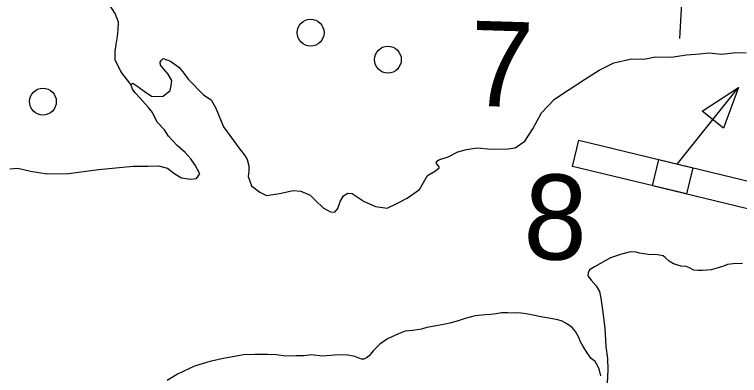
# Model space of a CAD drawing. Extents: x 653372 to 905732, y 627442 to 787275.
# Drawn here: x 702502 to 705201, y 742323 to 743667 of the extents above; entities that cross this region are included whole.
import ezdxf

# ---------------------------------------------------------------- set-up
doc = ezdxf.new("R2010")
doc.units = 0
for name, color, linetype in [('35', 7, 'Continuous'), ('5', 7, 'Continuous'), ('56', 7, 'Continuous'), ('57', 7, 'Continuous'), ('9', 7, 'Continuous')]:
    doc.layers.add(name, color=color, linetype=linetype)

msp = doc.modelspace()

# ---------------------------------------------------------------- linework, layer by layer
at = {"layer": '35'}
msp.add_lwpolyline([(702934.8, 743406.8), (702897.6, 743455.5), (702876.6, 743498.2), (702876.2, 743531.1), (702880.9, 743556), (702885.7, 743584.8), (702887.8, 743609.7), (702888.7, 743638.7), (702876.5, 743670.6), (702853.8, 743705.5), (702817.1, 743751.4), (702779.2, 743803.8), (702748.8, 743834.8)], dxfattribs=at)
at = {"layer": '5'}
msp.add_lwpolyline([(704993.4, 743866), (704977.1, 743578.3)], dxfattribs=at)
at = {"layer": '56'}
for p, q in [((705062, 743307.5), (705197.5, 743394.9)), ((705197.5, 743394.9), (705141.5, 743243.6)), ((705141.5, 743243.6), (705062, 743307.5))]:
    msp.add_line(p, q, dxfattribs=at)
msp.add_lwpolyline([(704969.1, 743110.4), (705197.5, 743394.9)], dxfattribs=at)
for points in [[(704578.7, 743101.8), (704602.2, 743199), (705027.5, 743096.3), (705004, 742999.1)], [(704876.9, 743029.8), (704900.4, 743127), (705325.7, 743024.2), (705302.2, 742927)]]:
    msp.add_lwpolyline(points, close=True, dxfattribs=at)
for centre in [(703604.2, 743599.6), (703891.9, 743499.2), (702607.6, 743343)]:
    msp.add_circle(centre, 50, dxfattribs=at)
at = {"layer": '9'}
for points in [[(703759, 743000.4), (703803.2, 742971.5), (703845.9, 742951.9), (703889, 742946.6), (703927.6, 742965.2), (703963.6, 742983.8), (704009.1, 743015.2), (704039.5, 743068.1), (704068.9, 743085.5), (704082.4, 743096.9), (704082.4, 743099.6), (704072.4, 743113), (704072.5, 743119.5), (704081.9, 743125.8), (704116.4, 743137.9), (704152.3, 743156.5), (704184.1, 743164.7), (704224.9, 743171.4), (704277.2, 743165.9), (704340.2, 743166.6), (704365.2, 743171.1), (704401.4, 743196.2), (704431.6, 743241.2), (704463.5, 743300.6), (704512.3, 743351.6), (704567.1, 743388), (704623.3, 743425.7), (704678.1, 743459.5), (704700.7, 743470.6), (704733.3, 743486.7), (704799.4, 743501.7), (704845.2, 743500.4), (704888.8, 743509.5), (704946.4, 743507.8), (705003.1, 743516.6), (705053, 743520.3), (705087.2, 743524.6), (705135.6, 743519.2), (705186.9, 743525.5), (705226.2, 743524.3)], [(703000.4, 743320.9), (702989, 743334.4), (702968.7, 743357.3), (702950.9, 743376.2), (702940.8, 743389.6), (702934.8, 743406.8), (702938.8, 743409.3), (702942.8, 743411.8), (702957, 743402.2), (702985.2, 743381.7), (703012.2, 743363.8), (703027.9, 743362), (703055.5, 743363.8), (703081, 743384.1), (703085.5, 743402.3), (703087.4, 743421.9), (703073.6, 743444.6), (703058.5, 743463.4), (703045.8, 743478.3), (703044.8, 743490.1), (703049, 743497.8), (703055.7, 743502.9), (703082.9, 743492.9), (703113.8, 743471), (703129, 743453.5), (703149.1, 743426.6), (703205.1, 743368.5), (703234.7, 743349.3), (703252.1, 743318.6), (703280.2, 743249.5), (703340.7, 743166.4), (703359.6, 743142.2), (703368.3, 743127.5), (703374.2, 743103.7), (703374.9, 743084), (703371.7, 743064.5), (703383.8, 743030), (703415.8, 743005.4), (703440.1, 742992.9), (703488.8, 743000.6), (703539, 743012.2), (703567.8, 743010.1), (703602.7, 742994.6), (703623.1, 742974.3), (703651.2, 742947.2), (703678.2, 742932), (703694, 742931.5), (703706.2, 742945.6), (703714.8, 742971.6), (703727.3, 742992.2), (703743.3, 743002.2), (703759, 743000.4)], [(702484.8, 743092.8), (702515, 743094.6), (702561.9, 743084), (702623.2, 743074.3), (702704.6, 743075.8), (702815.2, 743090.8), (702944, 743102.7), (702999.1, 743102.3), (703038.5, 743103.8), (703071, 743094.9), (703099.2, 743074.4), (703123.7, 743059.2), (703158.9, 743054.2), (703180, 743056.2), (703192.3, 743074.2), (703174.9, 743106.2), (703158.6, 743130.3), (703137, 743153.2), (703107.6, 743179), (703075.9, 743214.1), (703060.9, 743238.1), (703032.9, 743266.1), (703015.6, 743302.1), (703000.4, 743320.9)], [(705031, 742715.8), (705014.9, 742724.2), (705001.9, 742728.5), (704983.2, 742730.4), (704955.3, 742739.1), (704938.6, 742748.8), (704925.2, 742761), (704916.9, 742769.1), (704895.4, 742773), (704861.3, 742774.1), (704828.7, 742779), (704815.7, 742782.6), (704794.7, 742783.3), (704761.7, 742775.1), (704720.6, 742761.9), (704660.6, 742727.6), (704642.6, 742717), (704637, 742706), (704636, 742694.9), (704648.6, 742678.1), (704667, 742657.2), (704680.1, 742636.5), (704685.3, 742610.8), (704691.2, 742568), (704699, 742499.9), (704702.8, 742431.6), (704709.3, 742386.1), (704710.7, 742342.8), (704708.6, 742295.7)], [(705212.7, 742739.9), (705177.9, 742739), (705156.2, 742737), (705140.9, 742730.2), (705121.1, 742724.3), (705095.3, 742717.2), (705063.7, 742714.2), (705048, 742714), (705031, 742715.8)], [(704525, 742530.7), (704491.1, 742537), (704461.8, 742541.1), (704432.4, 742547.3), (704398.5, 742554.2), (704375.7, 742556.9), (704362.5, 742555.3), (704337.8, 742556.7), (704314.9, 742556.7), (704295.1, 742553.4), (704275.4, 742550.7), (704253.7, 742549.4), (704216.9, 742545.2), (704179.2, 742535.9), (704154, 742527.4), (704122.9, 742517.9), (704099.4, 742512.7), (704073, 742508.2), (704037.4, 742501.4), (704016.9, 742495.5), (703984.6, 742491.2), (703956.3, 742488.1), (703931.8, 742478.4), (703890.6, 742459.3), (703862.6, 742439.8), (703859.9, 742437.9), (703837.6, 742415), (703822.6, 742396.4), (703812.5, 742388.8), (703802.6, 742384.5), (703793.4, 742384.2), (703769.4, 742393.4), (703743.3, 742398.8), (703724.4, 742400.7), (703693, 742399), (703649, 742395.7), (703607.2, 742399.6), (703578.9, 742396.5), (703551.3, 742396), (703511.3, 742395.2), (703476.8, 742400.2), (703444.1, 742401.2), (703396.3, 742402), (703354.2, 742400), (703280.4, 742387.1), (703228.9, 742375.5), (703172.7, 742358.2), (703108.8, 742328), (703070.1, 742304.2)], [(704684.5, 742322), (704678.7, 742347.7), (704668.1, 742367), (704663.8, 742375.7), (704648.4, 742386.7), (704636.4, 742404.1), (704618.9, 742431.5), (704609.6, 742448.8), (704602.9, 742464.8), (704589.9, 742486.8), (704577.9, 742501.6), (704560.6, 742513.9), (704541.3, 742525), (704525, 742530.7)]]:
    msp.add_lwpolyline(points, dxfattribs=at)

# ---------------------------------------------------------------- texts
at = {"layer": '56'}
msp.add_text('8', height=316.8, rotation=358.28, dxfattribs=at).set_placement((704393.9, 742758.3))
at = {"layer": '57'}
msp.add_text('7', height=316.8, rotation=358.28, dxfattribs=at).set_placement((704193.1, 743327.9))

doc.saveas('drawing.dxf')
